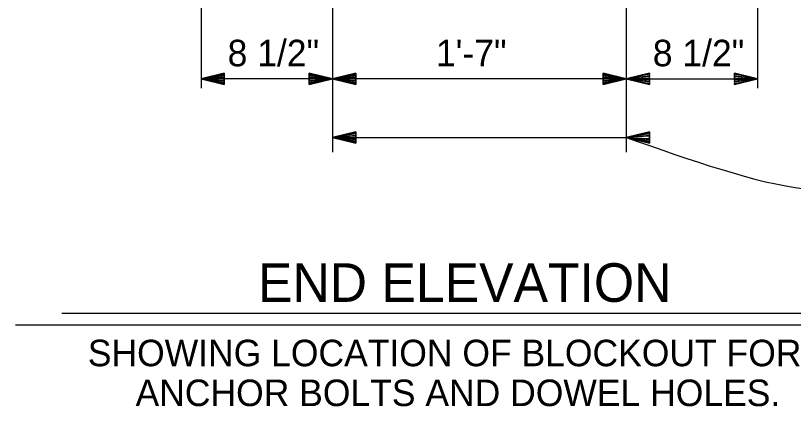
# Model space of a CAD drawing. Extents: x 0 to 177, y -1 to 130.
# Drawn here: x 49.766 to 53.959, y 13.281 to 15.391 of the extents above; entities that cross this region are included whole.
import ezdxf

# ---------------------------------------------------------------- set-up
doc = ezdxf.new("R2010")
doc.units = 0
for name, color, linetype in [('Dimension Lines', 7, 'Continuous'), ('Mis Center Lines', 7, 'Continuous'), ('Text', 7, 'Continuous'), ('Title Text', 7, 'Continuous')]:
    doc.layers.add(name, color=color, linetype=linetype)

msp = doc.modelspace()

# ---------------------------------------------------------------- linework, layer by layer
at = {"layer": 'Dimension Lines'}
for p, q in [((50.7662, 15.6118), (50.7662, 14.9994)), ((53.7662, 15.6118), (53.7662, 14.9994)), ((51.4746, 15.049), (50.7662, 15.049)), ((53.0579, 15.049), (51.4746, 15.049)), ((53.0579, 15.049), (53.7662, 15.049)), ((51.4746, 14.7328), (53.058, 14.7328))]:
    msp.add_line(p, q, dxfattribs=at)
for points in [[(50.8912, 15.049), (50.8912, 15.0553), (50.7662, 15.049), (50.8912, 15.0615), (50.8912, 15.0678), (50.7662, 15.049), (50.8912, 15.074), (50.8912, 15.0803), (50.7662, 15.049), (50.8912, 15.0178), (50.8912, 15.024), (50.7662, 15.049), (50.8912, 15.0303), (50.8912, 15.0365), (50.7662, 15.049), (50.8912, 15.0428), (50.8912, 15.0803), (50.8912, 15.0178), (50.7662, 15.049), (50.8912, 15.0803)], [(51.3496, 15.049), (51.3496, 15.0428), (51.4746, 15.049), (51.3496, 15.0365), (51.3496, 15.0303), (51.4746, 15.049), (51.3496, 15.024), (51.3496, 15.0178), (51.4746, 15.049), (51.3496, 15.0803), (51.3496, 15.074), (51.4746, 15.049), (51.3496, 15.0678), (51.3496, 15.0615), (51.4746, 15.049), (51.3496, 15.0553), (51.3496, 15.0178), (51.3496, 15.0803), (51.4746, 15.049), (51.3496, 15.0178)], [(51.5996, 15.049), (51.5996, 15.0553), (51.4746, 15.049), (51.5996, 15.0615), (51.5996, 15.0678), (51.4746, 15.049), (51.5996, 15.074), (51.5996, 15.0803), (51.4746, 15.049), (51.5996, 15.0178), (51.5996, 15.024), (51.4746, 15.049), (51.5996, 15.0303), (51.5996, 15.0365), (51.4746, 15.049), (51.5996, 15.0428), (51.5996, 15.0803), (51.5996, 15.0178), (51.4746, 15.049), (51.5996, 15.0803)], [(52.9329, 15.049), (52.9329, 15.0428), (53.0579, 15.049), (52.9329, 15.0365), (52.9329, 15.0303), (53.0579, 15.049), (52.9329, 15.024), (52.9329, 15.0178), (53.0579, 15.049), (52.9329, 15.0803), (52.9329, 15.074), (53.0579, 15.049), (52.9329, 15.0678), (52.9329, 15.0615), (53.0579, 15.049), (52.9329, 15.0553), (52.9329, 15.0178), (52.9329, 15.0803), (53.0579, 15.049), (52.9329, 15.0178)], [(53.1829, 15.049), (53.1829, 15.0428), (53.0579, 15.049), (53.1829, 15.0365), (53.1829, 15.0303), (53.0579, 15.049), (53.1829, 15.024), (53.1829, 15.0178), (53.0579, 15.049), (53.1829, 15.0803), (53.1829, 15.074), (53.0579, 15.049), (53.1829, 15.0678), (53.1829, 15.0615), (53.0579, 15.049), (53.1829, 15.0553), (53.1829, 15.0178), (53.1829, 15.0803), (53.0579, 15.049), (53.1829, 15.0178)], [(53.6412, 15.049), (53.6412, 15.0553), (53.7662, 15.049), (53.6412, 15.0615), (53.6412, 15.0678), (53.7662, 15.049), (53.6412, 15.074), (53.6412, 15.0803), (53.7662, 15.049), (53.6412, 15.0178), (53.6412, 15.024), (53.7662, 15.049), (53.6412, 15.0303), (53.6412, 15.0365), (53.7662, 15.049), (53.6412, 15.0428), (53.6412, 15.0803), (53.6412, 15.0178), (53.7662, 15.049), (53.6412, 15.0803)], [(51.5996, 14.7328), (51.5996, 14.739), (51.4746, 14.7328), (51.5996, 14.7453), (51.5996, 14.7515), (51.4746, 14.7328), (51.5996, 14.7578), (51.5996, 14.764), (51.4746, 14.7328), (51.5996, 14.7015), (51.5996, 14.7078), (51.4746, 14.7328), (51.5996, 14.714), (51.5996, 14.7203), (51.4746, 14.7328), (51.5996, 14.7265), (51.5996, 14.764), (51.5996, 14.7015), (51.4746, 14.7328), (51.5996, 14.764)], [(53.183, 14.7328), (53.183, 14.739), (53.058, 14.7328), (53.183, 14.7453), (53.183, 14.7515), (53.058, 14.7328), (53.183, 14.7578), (53.183, 14.764), (53.058, 14.7328), (53.183, 14.7015), (53.183, 14.7078), (53.058, 14.7328), (53.183, 14.714), (53.183, 14.7203), (53.058, 14.7328), (53.183, 14.7265), (53.183, 14.764), (53.183, 14.7015), (53.058, 14.7328), (53.183, 14.764)]]:
    msp.add_lwpolyline(points, dxfattribs=at)
msp.add_spline([(53.058, 14.7328), (54.4238, 14.7328), (54.4238, 15.1208), (54.6073, 15.1208)], degree=3, dxfattribs=at)
at = {"layer": 'Mis Center Lines'}
for p, q in [((51.4746, 16.4346), (51.4746, 14.6541)), ((53.0579, 16.4346), (53.0579, 14.6541))]:
    msp.add_line(p, q, dxfattribs=at)
at = {"layer": 'Title Text'}
for p, q in [((54.5162, 13.7828), (50.0162, 13.7828)), ((54.7662, 13.7203), (49.7662, 13.7203))]:
    msp.add_line(p, q, dxfattribs=at)

# ---------------------------------------------------------------- texts
at = {"layer": 'Text'}
for s, height, p in [('8 1/2"', 0.14302, (50.9093, 15.1168)), ('8 1/2"', 0.14302, (53.2009, 15.1168)), ('1\'-7"', 0.14302, (52.032, 15.1168)), ('SHOWING LOCATION OF BLOCKOUT FOR', 0.143021, (50.1557, 13.4985)), ('ANCHOR BOLTS AND DOWEL HOLES.', 0.143021, (50.413, 13.2835))]:
    msp.add_text(s, height=height, dxfattribs=at).set_placement(p)
at = {"layer": 'Title Text'}
msp.add_text('END ELEVATION', height=0.208281, dxfattribs=at).set_placement((51.0727, 13.8458))

doc.saveas('drawing.dxf')
